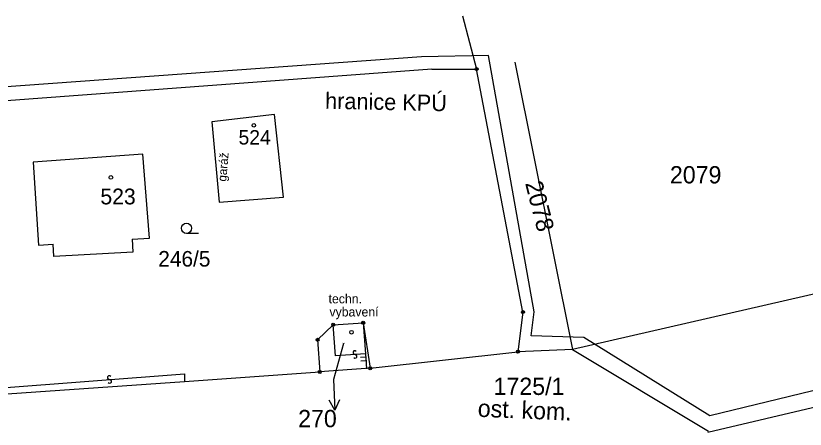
# Model space of a CAD drawing. Extents: x -815878 to -812162, y -1076286 to -1072327.
# Drawn here: x -813086.7 to -813009.2, y -1074210.3 to -1074169.7 of the extents above; entities that cross this region are included whole.
import ezdxf

# ---------------------------------------------------------------- set-up
doc = ezdxf.new("R2010")
doc.units = 0
for name, color, linetype in [('Vrstva 1', 7, 'Continuous'), ('Vrstva 16', 7, 'Continuous'), ('Vrstva 18', 7, 'Continuous'), ('Vrstva 19', 7, 'Continuous'), ('Vrstva 24', 7, 'Continuous'), ('Vrstva 25', 7, 'Continuous'), ('Vrstva 4', 7, 'Continuous'), ('Vrstva 56', 7, 'Continuous'), ('Vrstva 62', 7, 'Continuous')]:
    doc.layers.add(name, color=color, linetype=linetype)

msp = doc.modelspace()

# ---------------------------------------------------------------- linework, layer by layer
at = {"layer": 'Vrstva 1'}
for p, q in [((-813042.83, -1074169.67), (-813041.44, -1074174.91)), ((-813037.696, -1074174.241), (-813032.04, -1074202.46)), ((-813045.84, -1074174.91), (-813099.06, -1074178.89)), ((-813045.84, -1074174.91), (-813041.44, -1074174.91)), ((-813045.84, -1074174.91), (-813041.44, -1074174.91)), ((-813036.89, -1074198.78), (-813041.44, -1074174.91)), ((-813061.26, -1074179.38), (-813067.43, -1074180.1)), ((-813060.4, -1074187.48), (-813061.26, -1074179.38)), ((-813067.43, -1074180.1), (-813066.71, -1074187.98)), ((-812941.723, -1074181.649), (-813032.04, -1074202.46)), ((-813074.18, -1074183.26), (-813084.95, -1074184.06)), ((-813073.55, -1074191.51), (-813074.18, -1074183.26)), ((-813084.95, -1074184.06), (-813084.43, -1074192.19)), ((-813066.71, -1074187.98), (-813060.4, -1074187.48)), ((-813075.23, -1074191.62), (-813073.55, -1074191.51)), ((-813084.43, -1074192.19), (-813082.98, -1074192.1)), ((-813082.93, -1074193.32), (-813082.98, -1074192.1)), ((-813075.23, -1074191.62), (-813075.17, -1074192.88)), ((-813075.17, -1074192.88), (-813082.93, -1074193.32)), ((-813036.89, -1074198.78), (-813037.38, -1074202.67)), ((-813036.89, -1074198.78), (-813037.38, -1074202.67)), ((-813057.05, -1074201.5), (-813055.51, -1074200.02)), ((-813055.51, -1074200.02), (-813052.57, -1074199.82)), ((-813052.57, -1074199.82), (-813051.88, -1074204.3)), ((-813057.05, -1074201.5), (-813056.83, -1074204.66)), ((-813051.88, -1074204.3), (-813037.38, -1074202.67)), ((-813032.04, -1074202.46), (-813037.38, -1074202.67)), ((-813032.04, -1074202.46), (-813018.682, -1074210.482)), ((-813070.1, -1074205.59), (-813056.83, -1074204.66)), ((-813051.88, -1074204.3), (-813056.83, -1074204.66)), ((-813099.43, -1074207.64), (-813070.1, -1074205.59)), ((-813002.27, -1074206.74), (-813018.76, -1074210.61))]:
    msp.add_line(p, q, dxfattribs=at)
at = {"layer": 'Vrstva 16'}
for p, q in [((-813054.491, -1074201.85), (-813055.49, -1074205.41)), ((-813055.49, -1074205.41), (-813055.365, -1074208.407))]:
    msp.add_line(p, q, dxfattribs=at)
msp.add_lwpolyline([(-813054.907, -1074207.387), (-813055.365, -1074208.407), (-813055.906, -1074207.429)], dxfattribs=at)
at = {"layer": 'Vrstva 24'}
for centre, radius in [((-813041.44, -1074174.91), 0.15), ((-813041.44, -1074174.91), 0.075), ((-813036.89, -1074198.78), 0.15), ((-813036.89, -1074198.78), 0.075), ((-813055.51, -1074200.02), 0.15), ((-813055.51, -1074200.02), 0.075), ((-813052.57, -1074199.82), 0.15), ((-813052.57, -1074199.82), 0.075), ((-813057.05, -1074201.5), 0.15), ((-813057.05, -1074201.5), 0.075), ((-813037.38, -1074202.67), 0.15), ((-813037.38, -1074202.67), 0.075), ((-813056.83, -1074204.66), 0.15), ((-813056.83, -1074204.66), 0.075), ((-813051.88, -1074204.3), 0.15), ((-813051.88, -1074204.3), 0.075)]:
    msp.add_circle(centre, radius, dxfattribs=at)
at = {"layer": 'Vrstva 25'}
msp.add_line((-813068.738, -1074191.05), (-813069.91, -1074191.05), dxfattribs=at)
for centre, radius in [((-813063.3, -1074180.44), 0.175), ((-813077.33, -1074185.55), 0.175), ((-813069.91, -1074190.548), 0.503), ((-813053.72, -1074200.76), 0.175)]:
    msp.add_circle(centre, radius, dxfattribs=at)
at = {"layer": 'Vrstva 4'}
for p, q in [((-813055.3, -1074203.08), (-813055.51, -1074200.02)), ((-813052.57, -1074199.82), (-813052.35, -1074202.87)), ((-813052.35, -1074202.87), (-813055.3, -1074203.08)), ((-813052.35, -1074202.87), (-813052.25, -1074204.34)), ((-813099.42, -1074207.09), (-813070.12, -1074204.83)), ((-813070.12, -1074204.83), (-813070.1, -1074205.59))]:
    msp.add_line(p, q, dxfattribs=at)
at = {"layer": 'Vrstva 62'}
for p, q in [((-813046.84, -1074173.72), (-813098.74, -1074177.47)), ((-813040.27, -1074173.56), (-813046.84, -1074173.72)), ((-813035.78, -1074198.75), (-813040.27, -1074173.56)), ((-812926.48, -1074186.49), (-813018.56, -1074208.98)), ((-813036.1, -1074201.12), (-813035.78, -1074198.75)), ((-813030.91, -1074201.26), (-813036.1, -1074201.12)), ((-813018.56, -1074208.98), (-813030.91, -1074201.26)), ((-813052.829, -1074203.219), (-813052.231, -1074203.178)), ((-813052.805, -1074203.578), (-813052.206, -1074203.537))]:
    msp.add_line(p, q, dxfattribs=at)
for centre, start, end in [((-813053.384, -1074202.759), 41.44455, 273.54254), ((-813053.36, -1074203.126), 221.23009, 93.82009), ((-813077.479, -1074205.213), 41.56895, 274.15895), ((-813077.453, -1074205.581), 221.7834, 93.8814)]:
    msp.add_arc(centre, 0.184, start, end, dxfattribs=at)

# ---------------------------------------------------------------- texts
at = {"layer": 'Vrstva 16'}
msp.add_text('270', height=1.7, dxfattribs=at).set_placement((-813058.954, -1074210.09))
at = {"layer": 'Vrstva 18'}
for s, height, p in [('2079', 1.7, (-813022.47, -1074186.14)), ('246/5', 1.5296, (-813072.68, -1074194.31)), ('1725/1', 1.7, (-813039.774, -1074206.92))]:
    msp.add_text(s, height=height, dxfattribs=at).set_placement(p)
msp.add_text('2078', height=1.7, rotation=284.4, dxfattribs=at).set_placement((-813036.69, -1074186.12))
at = {"layer": 'Vrstva 19'}
for s, height, p in [('524', 1.4167, (-813064.803, -1074182.32)), ('523', 1.5528, (-813078.36, -1074188.2)), ('270', 0.1, (-813054.598, -1074201.9))]:
    msp.add_text(s, height=height, dxfattribs=at).set_placement(p)
at = {"layer": 'Vrstva 56'}
for s, height, rotation, p in [('hranice KPÚ', 1.59202, 358.78291, (-813056.32, -1074178.8)), ('garáž', 0.85, 85.12093, (-813066.015, -1074185.977)), ('ost. kom. ', 1.7, 357.60503, (-813041.354, -1074209.057))]:
    msp.add_text(s, height=height, rotation=rotation, dxfattribs=at).set_placement(p)
for s, p in [('techn.', (-813055.97, -1074197.92)), ('vybavení', (-813055.88, -1074199.21))]:
    msp.add_text(s, height=0.9, dxfattribs=at).set_placement(p)

doc.saveas('drawing.dxf')
